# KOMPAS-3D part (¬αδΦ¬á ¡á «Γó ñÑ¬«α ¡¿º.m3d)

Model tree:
1. Эскиз:1
2. Операция выдавливания:1
     Расстояние 1 = 2
3. Эскиз:2
4. Вырезать элемент выдавливания:1
     Расстояние 1 = 10; Угол 1 = 35
5. Эскиз:3
6. Вырезать элемент выдавливания:2
     Расстояние 1 = 10
